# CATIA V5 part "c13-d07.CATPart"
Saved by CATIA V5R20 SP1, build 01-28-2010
Part number: Part1
Bounding box of the stored display mesh (mm): x -49.812 to 35, y -44.222 to 44.222, z 0 to 30
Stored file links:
  D:\v5_r20\psrt_files_downloaded\c13-catia-v5r20-prt\Figure 13-27\c13-d07.CATPart
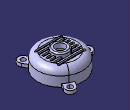
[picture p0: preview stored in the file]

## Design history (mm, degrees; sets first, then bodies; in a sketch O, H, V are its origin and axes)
Body1 (main body)
  Sketch1 on yz-plane, origin (0, 0, 0), H (0, 1, 0), V (0, 0, 1)
    line L1 (0, 0) -> (35, 0)
    line L2 (35, 0) -> (35, 15)
    arc A1 centre (25, 15) radius 10 from (35, 15) to (25, 25) ccw
    line L3 (25, 25) -> (0, 25)
    point P5 (0, 25)
    line L4 (0, 25) -> (0, 0)
    axis line L5 (0, 70.1891) -> (0, -36.6898)
    point P6 (0, 70.1891)
    "Radius" L2 L5 = 35
    distance L1 L3 = 25
    radius A1 = 10
    horizontal: L1 H
    vertical: L2 V, L4 V, L5 V
    tangency: A1 L2, L3 A1
    coincidence: P5 V, P6 V
  Shaft1: profile Sketch1, axis Sketch1.L5, angle 360
  Shell1: IntOffset 2.5, Face face of Shaft1, ExtOffset 0
  Sketch2 on face of Shaft1, origin (0, 0, 0), H (1, 0, 0), V (0, -1, 0)
    projected circle E1 centre (0, 0) radius 35 from edge [face of Shaft1 | face of Shaft1]
    projected arc E2 centre (0, 0) radius 35 from (-34.187, 7.5) to (-34.187, -7.5) ccw from edge [face of Shaft1 | face of Shaft1]
    point P1 (-34.187, 7.5)
    line L1 (-34.187, 7.5) -> (-42.5, 7.5)
    arc A1 centre (-42.5, 0) radius 7.5 from (-42.5, 7.5) to (-42.5, -7.5) ccw
    point P3 (-42.5, 0)
    line L2 (-42.5, -7.5) -> (-34.187, -7.5)
    point P5 (-34.187, -7.5)
    circle A2 centre (-42.5, 0) radius 3.75
    distance P3 V = 42.5
    radius A1 = 7.5
    radius A2 = 3.75
    coincidence: P1 E1, P5 E1, P3 H
    horizontal: L1 H, L2 H
    tangency: A1 L1, L2 A1
  Pad1: profile Sketch2, direction (0, 0, 1), length 5
  CircPattern1: of Pad1, instances 3, angular step 120 {= 360.0*1 deg/CircPattern1.AngularNumber}, axis from face of Shaft1
  Sketch3 on face of Shaft1, origin (0, 0, 25), H (1, 0, 0), V (0, 1, 0)
    construction line L1 (-20, -18) -> (20, -18)
    point P2 (20, -18)
    line L2 (-20, -16.25) -> (20, -16.25)
    line L3 (20, -19.75) -> (-20, -19.75)
    arc A1 centre (20, -18) radius 1.75 from (20, -16.25) to (20, -19.75) cw
    arc A2 centre (-20, -18) radius 1.75 from (-20, -19.75) to (-20, -16.25) cw
    length L1 = 40
    distance H L1 = 18
    distance P2 V = 20
    distance L3 L2 = 3.5
    horizontal: L1 H
    tangency: A1 L2, A2 L2, A1 L3, A2 L3
    parallelism: L1 L2
  Pocket1: profile Sketch3, direction (0, 0, -1), through (limit type 3)
  RectPattern1: of Pocket1, direction 1 instances 7, spacing 6, along yz-plane
  Sketch4 on yz-plane, origin (0, 0, 0), H (0, 1, 0), V (0, 0, 1)
    axis line L1 (0, 0) -> (0, 35.5018)
    point P2 (0, 22.5)
    line L2 (0, 22.5) -> (12.5, 22.5)
    line L3 (12.5, 22.5) -> (12.5, 28)
    arc A1 centre (10.5, 28) radius 2 from (12.5, 28) to (10.5, 30) ccw
    line L4 (10.5, 30) -> (0, 30)
    point P7 (0, 30)
    line L5 (0, 30) -> (0, 22.5)
    reference intersected line E1 (25, 22.5) -> (-25, 22.5) from face of Shell1
    "Radius" L3 L1 = 12.5
    distance L4 L2 = 7.5
    radius A1 = 2
    vertical: L1 V, L3 V, L5 V
    coincidence: P2 L1, P7 L1, L2 E1
    horizontal: L2 H, L4 H
    tangency: A1 L3, L4 A1
  Shaft2: profile Sketch4, axis Sketch4.L1, angle 360
  Sketch5 on face of Shaft2, origin (0, 0, 30), H (1, 0, 0), V (0, 1, 0)
    point P1 (0, 0)
    reference projected circle E1 centre (0, 0) radius 12.5 from edge [face of Shaft2 | face of Shaft2]
    concentricity: P1 E1
  Hole1: placed by Sketch5, at (0, 0, 30) direction (0, 0, -1), diameter 15, through (limit type 3)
